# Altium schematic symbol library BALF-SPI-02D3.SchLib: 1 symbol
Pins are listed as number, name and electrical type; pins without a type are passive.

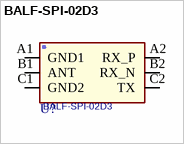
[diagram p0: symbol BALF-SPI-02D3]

## BALF-SPI-02D3
designator U?
footprint ST_CSP06N50P3X2_140X200X65
pins: A1 GND1, A2 RX_P, B1 ANT, B2 RX_N, C1 GND2, C2 TX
